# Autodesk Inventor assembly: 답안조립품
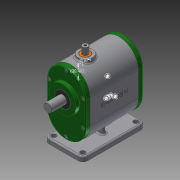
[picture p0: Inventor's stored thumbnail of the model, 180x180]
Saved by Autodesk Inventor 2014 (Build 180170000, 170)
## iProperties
Created: 2016-12
Part Number: 답안조립품
Document SubType Name: Assembly
Designer: user
Author: user
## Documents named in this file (14)
- C:\Users\user\Desktop\361208V1019\답안조립품.iam
- C:\Users\user\Desktop\361208V1019\본체.ipt
- C:\Users\user\Desktop\361208V1019\앞커버.ipt
- C:\Users\user\Desktop\361208V1019\뒤커버.ipt
- C:\Users\user\Desktop\361208V1019\베어링 6003.ipt
- C:\Users\user\Desktop\361208V1019\베어링 608.ipt
- C:\Users\user\Desktop\361208V1019\오일실 17 32 8.ipt
- C:\Users\user\Desktop\361208V1019\오일실 8 22 7.ipt
- C:\Users\user\Desktop\361208V1019\서브축.ipt
- C:\Users\user\Desktop\361208V1019\메인축.ipt
- C:\Users\user\Desktop\361208V1019\부시.ipt
- C:\Users\user\Desktop\361208V1019\슬라이더.ipt
- C:\Users\user\Desktop\361208V1019\가변스프링.ipt
- C:\Users\user\Desktop\361208V1019\볼트 M4.ipt
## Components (1 placed, 1 different names)
1. 가변스프링:1 — Mate:4, Mate:5, Mate:6
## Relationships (3: Mate 3)
- Mate:4: 가변스프링:1
- Mate:5: 가변스프링:1
- Mate:6: 가변스프링:1
